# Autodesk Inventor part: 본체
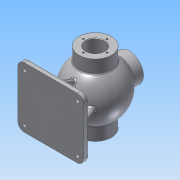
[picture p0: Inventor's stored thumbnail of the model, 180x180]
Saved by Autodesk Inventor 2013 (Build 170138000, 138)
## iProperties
Created: 2018-06
Part Number: 본체
Material: 알루미늄 6061
Document SubType Name: Modeling
Designer: Administrator
Mass: 1509.66 g
Surface Area: 1153.69 cm^2
Volume: 557.069 cm^3
Density: 2.71 g/cm^3
Author: Administrator
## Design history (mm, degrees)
sketch "스케치1"
  geometry: L1 (0, 53)-(0, -53); A1 r 53 centre (0, 0) between (0, -53) and (0, 53); 2 further points
  constraints: 2 coincident, 2 end point, 2 point on circle, 1 centre point, 1 midpoint, 1 vertical
  dimensions: "d0" = 106 distance of L1.start L1.end
revolve "회전1" sketch "스케치1" stored, may be unused: angle "d3" = 90 deg
sketch "스케치2"
  geometry: L1 (0, 43)-(0, -43); A1 r 43 centre (0, 0) between (0, -43) and (0, 43); 2 further points
  constraints: 2 coincident, 2 end point, 2 point on circle, 1 centre point, 1 midpoint, 1 vertical
  dimensions: "d4" = 86 distance of L1.start L1.end
revolve "회전2" sketch "스케치2" stored, may be unused: angle "d7" = 90 deg
node "작업 평면1"
sketch "스케치3"
  geometry: C1 r 31 at (0, 0); 1 further point
  constraints: 1 centre point, 1 coincident
  dimensions: "d9" = 62 diameter of C1
extrude "돌출1" join sketch "스케치3" stored distance "d10" = 10; taper "d11" = 0 deg
node "작업 평면2"
sketch "스케치6"
  geometry: C1 r 31 at (0, 0); 1 further point
  constraints: 1 centre point, 1 coincident
  dimensions: "d27" = 62 diameter of C1
extrude "돌출3" join sketch "스케치6" stored distance "d28" = 10; taper "d29" = 0 deg
sketch "스케치7"
  geometry: C1 r 31 at (0, 0) reference; C2 r 17.5 at (0, 0)
  constraints: 1 centre point, 1 coincident
  dimensions: "d30" = 35 diameter of C2
extrude "돌출4" cut sketch "스케치7" stored distance "d31" = 10; taper "d32" = 0 deg
node "작업 평면3"
sketch "스케치10"
  geometry: C1 r 18.5 at (0, 0); 1 further point
  constraints: 1 centre point, 1 coincident
  dimensions: "d37" = 37 diameter of C1
extrude "돌출6" cut sketch "스케치10" distance "d38" = 1.75; taper "d39" = 0 deg
node "작업 평면4"
sketch "스케치11"
  geometry: C1 r 27 at (0, 0); 1 further point
  constraints: 1 centre point, 1 coincident
  dimensions: "d41" = 54 diameter of C1
extrude "돌출7" join sketch "스케치11" stored distance "d42" = 1.5; taper "d43" = 0 deg
sketch "스케치12"
  geometry: C1 r 17.5 at (0, 0) reference; C2 r 31 at (0, 0) reference; 1 further point
  constraints: 1 vertical alignment
  dimensions: "d44" = 22.5 distance of point (0, 22.5) C2.centre
hole "구멍2" sketch "스케치12" at (0, 22.5) diameter "d45" = 3.242; stored, may be unused: countersink angle "d49" = 90 deg, drill point angle "d51" = 118 deg; dims "d46" = 12, "d47" = 4, "d48" = 2, "d50" = 15
sketch "스케치13"
  geometry: C1 r 17.5 at (0, 0) reference; 1 further point
  constraints: 1 vertical alignment
  dimensions: "d55" = 24 distance of point (0, 24) C1.centre
hole "구멍3" sketch "스케치13" at (0, 24) diameter "d56" = 3.242; stored, may be unused: countersink angle "d60" = 90 deg, drill point angle "d62" = 118 deg; dims "d57" = 16, "d58" = 4, "d59" = 2, "d61" = 19
sketch "스케치14"
  geometry: C1 r 27 at (0, 0) reference; 1 further point
  constraints: 1 vertical alignment
  dimensions: "d66" = 20 distance of C1.centre point (0, 20)
hole "구멍4" sketch "스케치14" at (0, 20) diameter "d67" = 3.242; stored, may be unused: countersink angle "d71" = 90 deg, drill point angle "d73" = 118 deg; dims "d68" = 9, "d69" = 4, "d70" = 2, "d72" = 11
sketch "스케치15"
  geometry: C1 r 27 at (0, 0) reference; C2 r 13 at (0, 0)
  constraints: 1 centre point, 1 coincident
  dimensions: "d77" = 26 diameter of C2
extrude "돌출8" cut sketch "스케치15" stored distance "d78" = 1.5; taper "d79" = 0 deg
node "작업 평면5"
sketch "스케치16"
  geometry: L1 (-62.5, 57.5)-(62.5, 57.5); L2 (62.5, 57.5)-(62.5, -57.5); L3 (62.5, -57.5)-(-62.5, -57.5); L4 (-62.5, -57.5)-(-62.5, 57.5); L5 (-62.5, 57.5)-(62.5, -57.5); L6 (62.5, 57.5)-(-62.5, -57.5); 1 further point
  constraints: 12 end point, 2 midpoint, 2 parallel, 1 horizontal, 1 perpendicular
  dimensions: "d81" = 125 distance of L2.end L3.end; "d82" = 115 distance of L1.end L2.end
extrude "돌출9" join sketch "스케치16" distance "d83" = 10; taper "d84" = 0 deg
fillet "모깎기1" dims "d85" = 12
hole "구멍5" diameter "d88" = 8; stored, may be unused: countersink angle "d92" = 90 deg, drill point angle "d94" = 0 deg; dims "d86" = 10, "d87" = 10, "d89" = 9, "d90" = 12, "d91" = 3, "d93" = 11
hole "구멍6" diameter "d97" = 8; stored, may be unused: countersink angle "d101" = 90 deg, drill point angle "d103" = 0 deg; dims "d95" = 10, "d96" = 10, "d98" = 9, "d99" = 12, "d100" = 3, "d102" = 11
hole "구멍7" diameter "d106" = 8; stored, may be unused: countersink angle "d110" = 90 deg, drill point angle "d112" = 0 deg; dims "d104" = 10, "d105" = 10, "d107" = 9, "d108" = 12, "d109" = 3, "d111" = 11
hole "구멍8" diameter "d115" = 8; stored, may be unused: countersink angle "d119" = 90 deg, drill point angle "d121" = 0 deg; dims "d113" = 10, "d114" = 10, "d116" = 9, "d117" = 12, "d118" = 3, "d120" = 11
sketch "스케치17"
  geometry: L1 (-4, -4)-(4, -4); L2 (4, -4)-(4, 4); L3 (4, 4)-(-4, 4); L4 (-4, 4)-(-4, -4); L5 (-4, -4)-(4, 4); L6 (4, -4)-(-4, 4); 1 further point
  constraints: 12 end point, 2 midpoint, 2 parallel, 1 horizontal, 1 perpendicular
  dimensions: "d122" = 8 distance of L3.end L2.end; "d123" = 8 distance of L2.end L1.end
extrude "돌출10" join sketch "스케치17" stored distance "d124" = 10; taper "d125" = 0 deg
sketch "스케치18"
  geometry: L1 (-52.5, -75)-(-42.226, -49.571); L2 (-62.5, -75)-(-62.5, -85) reference; L3 (-56.5, -75)-(-44.5, -75) reference; L4 (-62.5, -75)-(-50.5, -75) reference; 1 further point
  constraints: 2 end point, 1 point on line
  dimensions: "d126" = 10 distance from line of L1.start L2; "d127" = 112 deg angle of L1 L4
feature "리브1" sketch "스케치18" dims "d128" = 1, "d129" = 8, "d130" = 0, "d131" = 0, "d132" = 1, "d133" = 1
sketch "스케치19"
  geometry: L1 (-75, -47.5)-(-48.113, -36.637); L2 (-75, -57.5)-(-85, -57.5) reference; L3 (-75, -39.5)-(-75, -51.5) reference; L4 (-75, -45.5)-(-75, -57.5) reference; 1 further point
  constraints: 2 end point, 1 point on line
  dimensions: "d134" = 10 distance from line of L2 L1.start; "d135" = 112 deg angle of L4 L1
feature "리브2" sketch "스케치19" dims "d136" = 1, "d137" = 8, "d138" = 0, "d139" = 0, "d140" = 1, "d141" = 1
chamfer "모따기1" distance "d142" = 1; stored, may be unused: second distance "d143" = 2, angle "d144" = 45 deg
fillet "모깎기2" dims "d145" = 3
fillet "모깎기3" dims "d146" = 3
node "작업 평면8"
sketch "스케치21"
  geometry: L1 (0, -27)-(0, 27) reference; 2 further points
  constraints: 1 other
  dimensions: "d151" = 10 distance from line of point (10, 0) L1; "d152" = 27 vertical distance of point (10, 0) L1.start
feature "엠보싱2" sketch "스케치21" dims "d153" = 0.5, "d154" = 0
node "솔리드1"
pattern_circular "원형 패턴2" dims angle "d53" = 360 deg
pattern_circular "원형 패턴3" dims angle "d64" = 360 deg
pattern_circular "원형 패턴4" dims angle "d75" = 360 deg
mirror "대칭1"
mirror "대칭2"
other parameters: "d8" = 68, "d26" = -68, "d36" = -16, "d40" = 65, "d80" = -85
